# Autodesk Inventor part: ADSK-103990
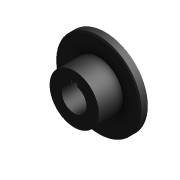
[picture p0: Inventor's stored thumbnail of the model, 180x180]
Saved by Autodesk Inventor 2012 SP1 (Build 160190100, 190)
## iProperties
Shininess: 0.0
Created: 2000-11
Part Number: ADSK-103990
Description: Sproket H60P20 Bore = 1-1/2" c/w KEYWAY
Document SubType Name: Modeling
Stock Number: ADSK-103990
Density: 1 g/cm^3
Material: Default
Density: 0.0
Volumn: 0.0
Area: 0.0
PropertySet Name: Model Information
Control State: 0
Master: False
Checked Out: False
Author: gao
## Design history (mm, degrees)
node "Extrusion1" dims "d1" = 11.6586, "d2" = 0
  sketch "Sketch1"
    geometry: C1 r 65.913 at (-0.585, -0.634)
    constraints: 1 centre point
    dimensions: "d0" = 131.826 diameter of C1
node "Extrusion2" dims "d4" = 37.3126, "d5" = 0
  sketch "Sketch2"
    geometry: C1 r 65.913 at (0, 0) reference; C2 r 38.1 at (0, 0)
    constraints: 1 centre point, 1 coincident
    dimensions: "d3" = 76.2 diameter of C2
node "Hole1" dims "d6" = 38.1, "d7" = 9.525, "d8" = 6.35, "d9" = 60 deg, "d10" = 19.05, "d11" = 118 deg
  sketch "Sketch3"
    geometry: C1 r 38.1 at (0, 0) reference; 1 further point
    constraints: 1 coincident
node "Chamfer1" dims "d12" = 3.175, "d13" = 15 deg, "d21" = 3.175
node "Chamfer2" dims "d14" = 3.175, "d15" = 15 deg, "d22" = 3.175
node "Extrusion3" dims "d19" = 25.4, "d20" = 0
  sketch "Sketch4"
    geometry: L1 (-4.763, 18.445)-(4.762, 18.445); L2 (4.762, 18.445)-(4.762, 23.208); L3 (4.762, 23.208)-(-4.763, 23.208); L4 (-4.763, 23.208)-(-4.763, 18.445); 1 further point
    constraints: 8 end point, 2 parallel, 1 horizontal, 1 perpendicular, 2 other
    dimensions: "d16" = 4.7625 distance from line of L4 point (0, 0); "d17" = 9.525 distance of L2.end L3.end; "d18" = 4.7625 distance of L1.end L2.end (= d16)
body "Solid1"
